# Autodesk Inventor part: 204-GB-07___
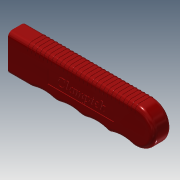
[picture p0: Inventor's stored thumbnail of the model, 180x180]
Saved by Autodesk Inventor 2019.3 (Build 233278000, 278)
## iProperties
Created: 2010-06
Part Number: 204-GB-07___
Material: Ogólny
Document SubType Name: Modeling
Designer: CADENGINEERING4
Density: 1 g/cm^3
Appearance: Czerwona
Author: CADENGINEERING4
Revision Number: ANY
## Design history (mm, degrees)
feature "NONE"
node "Bryła1"
